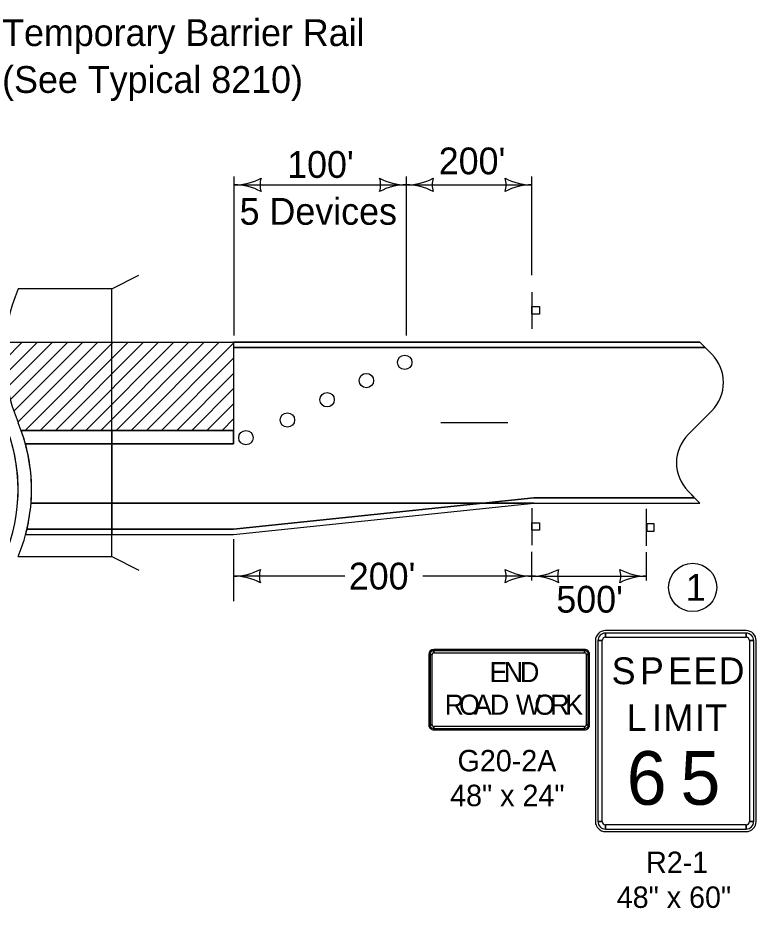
# Model space of a CAD drawing. Extents: x 10133 to 2270741, y 5363 to 1733450.
# Drawn here: x 27102 to 27653, y 11292 to 11957 of the extents above; entities that cross this region are included whole.
import ezdxf

# ---------------------------------------------------------------- set-up
doc = ezdxf.new("R2010")
doc.units = 0
for name, color, linetype in [('dsnNonPlotable', 7, 'Continuous'), ('dsnShtPlotShapeBatchPrint', 7, 'Continuous'), ('dsnStdBorder', 7, 'Continuous'), ('Level 12', 7, 'Continuous'), ('Level 2', 7, 'Continuous')]:
    doc.layers.add(name, color=color, linetype=linetype)

msp = doc.modelspace()

# ---------------------------------------------------------------- linework, layer by layer
at = {"layer": 'dsnNonPlotable'}
for p, q in [((27172.24, 11754.35), (27192.24, 11764.35)), ((27619.84, 11705.56), (27611.06, 11714.35)), ((27602.27, 11645.56), (27619.84, 11663.13)), ((27104.47, 11648.61), (27263, 11648.61)), ((27263, 11648.61), (27263, 11638.61)), ((27263, 11638.61), (27107.64, 11638.61)), ((27611.06, 11594.35), (27602.27, 11603.13)), ((27111.86, 11594.35), (27487.22, 11594.35)), ((27263, 11574.84), (27487.2, 11598.35)), ((27108.85, 11574.84), (27263, 11574.84)), ((27102.24, 11554.35), (27172.24, 11554.35)), ((27172.24, 11554.35), (27192.24, 11544.35))]:
    msp.add_line(p, q, dxfattribs=at)
for points in [[(27172.24, 11554.35), (27172.24, 11754.35), (27102.24, 11754.35)], [(27263, 11710.35), (27615.06, 11710.35)], [(27417.67, 11654.35), (27467.67, 11654.35)], [(27417.67, 11654.35), (27467.67, 11654.35)], [(27104.47, 11648.61), (27117.54, 11648.61)], [(27120.71, 11638.61), (27107.64, 11638.61)], [(27487.2, 11598.35), (27607.06, 11598.35)]]:
    msp.add_lwpolyline(points, dxfattribs=at)
for centre, radius, start, end in [((27222.24, 11704.35), 130, 157.38014, 202.61987), ((27598.63, 11684.35), 30, 315, 45), ((26972.24, 11604.35), 130, 337.38014, 22.61987), ((26982.24, 11604.34), 130, 337.38014, 22.61987), ((27623.48, 11624.35), 30, 135, 225)]:
    msp.add_arc(centre, radius, start, end, dxfattribs=at)
at = {"layer": 'dsnShtPlotShapeBatchPrint'}
msp.add_circle((27605.63, 11531.37), 18, dxfattribs=at)
at = {"layer": 'dsnStdBorder'}
for p, q in [((27485.62, 11751.88), (27485.62, 11724.38)), ((27092.28, 11701.37), (27105.26, 11714.35)), ((27092.96, 11690.73), (27116.57, 11714.35)), ((27094.38, 11680.85), (27127.88, 11714.35)), ((27096.44, 11671.59), (27139.2, 11714.35)), ((27099.04, 11662.87), (27150.51, 11714.35)), ((27102.12, 11654.64), (27161.82, 11714.35)), ((27107.4, 11648.61), (27173.14, 11714.35)), ((27118.72, 11648.61), (27184.45, 11714.35)), ((27130.03, 11648.61), (27195.77, 11714.35)), ((27141.35, 11648.61), (27207.08, 11714.35)), ((27152.66, 11648.61), (27218.39, 11714.35)), ((27163.97, 11648.61), (27229.71, 11714.35)), ((27175.29, 11648.61), (27241.02, 11714.35)), ((27186.6, 11648.61), (27252.33, 11714.35)), ((27197.91, 11648.61), (27263, 11713.7)), ((27263, 11714.35), (27263, 11648.61)), ((27209.23, 11648.61), (27263, 11702.39)), ((27220.54, 11648.61), (27263, 11691.07)), ((27231.86, 11648.61), (27263, 11679.76)), ((27243.17, 11648.61), (27263, 11668.45)), ((27254.48, 11648.61), (27263, 11657.13)), ((27172.24, 11648.61), (27172.24, 11638.61)), ((27263, 11638.61), (27263, 11648.61)), ((27172.24, 11638.61), (27263, 11638.61)), ((27263, 11574.84), (27487.2, 11598.35)), ((27487.2, 11598.35), (27607.06, 11598.35)), ((27485.62, 11590.44), (27485.62, 11562.94)), ((27571.27, 11562.46), (27571.27, 11589.96)), ((27645.52, 11499.13), (27540.52, 11499.13)), ((27540.52, 11494.13), (27540.52, 11497.26)), ((27645.52, 11497.26), (27645.52, 11494.13)), ((27533.02, 11491.63), (27533.02, 11356.63)), ((27534.89, 11491.63), (27538.02, 11491.63)), ((27648.02, 11491.63), (27651.14, 11491.63)), ((27653.02, 11356.63), (27653.02, 11491.63)), ((27408.68, 11481.31), (27408.68, 11428.81)), ((27409.62, 11481.31), (27411.18, 11481.31)), ((27524.93, 11485.06), (27412.43, 11485.06)), ((27412.43, 11482.56), (27412.43, 11484.12)), ((27524.93, 11484.12), (27524.93, 11482.56)), ((27526.18, 11481.31), (27527.75, 11481.31)), ((27528.68, 11428.81), (27528.68, 11481.31)), ((27411.18, 11428.81), (27409.62, 11428.81)), ((27412.43, 11426), (27412.43, 11427.56)), ((27524.93, 11427.56), (27524.93, 11426)), ((27527.75, 11428.81), (27526.18, 11428.81)), ((27412.43, 11425.06), (27524.93, 11425.06)), ((27538.02, 11356.63), (27534.89, 11356.63)), ((27540.52, 11351.01), (27540.52, 11354.13)), ((27645.52, 11354.13), (27645.52, 11351.01)), ((27651.14, 11356.63), (27648.02, 11356.63)), ((27540.52, 11349.13), (27645.52, 11349.13))]:
    msp.add_line(p, q, dxfattribs=at)
for points in [[(27485.71, 11735.43), (27485.71, 11741.06), (27491.34, 11741.06), (27491.34, 11735.43)], [(27485.71, 11573.99), (27485.71, 11579.61), (27491.34, 11579.61), (27491.34, 11573.99)], [(27571.36, 11578.91), (27571.36, 11573.29), (27576.99, 11573.29), (27576.99, 11578.91)], [(27645.52, 11497.26), (27540.52, 11497.26), (27540.52, 11494.13), (27645.52, 11494.13), (27645.52, 11497.26)], [(27534.89, 11491.63), (27534.89, 11356.63), (27538.02, 11356.63), (27538.02, 11491.63), (27534.89, 11491.63)], [(27651.14, 11356.63), (27651.14, 11491.63), (27648.02, 11491.63), (27648.02, 11356.63), (27651.14, 11356.63)], [(27409.62, 11481.31), (27409.62, 11428.81), (27411.18, 11428.81), (27411.18, 11481.31), (27409.62, 11481.31)], [(27524.93, 11484.12), (27412.43, 11484.12), (27412.43, 11482.56), (27524.93, 11482.56), (27524.93, 11484.12)], [(27527.75, 11428.81), (27527.75, 11481.31), (27526.18, 11481.31), (27526.18, 11428.81), (27527.75, 11428.81)], [(27412.43, 11426), (27524.93, 11426), (27524.93, 11427.56), (27412.43, 11427.56), (27412.43, 11426)], [(27540.52, 11351.01), (27645.52, 11351.01), (27645.52, 11354.13), (27540.52, 11354.13), (27540.52, 11351.01)]]:
    msp.add_lwpolyline(points, close=True, dxfattribs=at)
msp.add_lwpolyline([(27263, 11648.61), (27254.48, 11648.61), (27243.17, 11648.61), (27231.86, 11648.61), (27220.54, 11648.61), (27209.23, 11648.61), (27197.91, 11648.61), (27186.6, 11648.61), (27175.29, 11648.61), (27172.24, 11648.61)], dxfattribs=at)
for centre in [(27390.73, 11699.38), (27390.73, 11699.38), (27362.14, 11685.77), (27362.14, 11685.77), (27332.81, 11671.46), (27332.81, 11671.46), (27303.19, 11656.36), (27303.19, 11656.36), (27272.23, 11643.14), (27272.23, 11643.14)]:
    msp.add_circle(centre, 5.37, dxfattribs=at)
for centre, radius, start, end in [((27540.52, 11491.63), 7.5, 90.00021, 179.99985), ((27645.52, 11491.63), 7.5, 0, 90.00021), ((27540.52, 11491.63), 5.62, 90.00021, 179.99985), ((27540.52, 11491.63), 2.5, 90.00021, 179.99985), ((27645.52, 11491.63), 5.62, 0, 90.00021), ((27645.52, 11491.63), 2.5, 0, 90.00021), ((27412.43, 11481.31), 3.75, 90.00021, 179.99985), ((27412.43, 11481.31), 2.81, 90.00021, 179.99985), ((27412.43, 11481.31), 1.25, 90.00021, 179.99985), ((27524.93, 11481.31), 3.75, 0, 90.00021), ((27524.93, 11481.31), 2.81, 0, 90.00021), ((27524.93, 11481.31), 1.25, 0, 90.00021), ((27412.43, 11428.81), 3.75, 179.99985, 270.00006), ((27412.43, 11428.81), 2.81, 179.99985, 270.00006), ((27412.43, 11428.81), 1.25, 179.99985, 270.00006), ((27524.93, 11428.81), 3.75, 270.00006, 0.00027), ((27524.93, 11428.81), 2.81, 270.00006, 0.00027), ((27524.93, 11428.81), 1.25, 270.00006, 0.00027), ((27540.52, 11356.63), 7.5, 179.99985, 270.00006), ((27540.52, 11356.63), 5.62, 179.99985, 270.00006), ((27540.52, 11356.63), 2.5, 179.99985, 270.00006), ((27645.52, 11356.63), 7.5, 270.00006, 0.00027), ((27645.52, 11356.63), 5.62, 270.00006, 0.00027), ((27645.52, 11356.63), 2.5, 270.00006, 0.00027)]:
    msp.add_arc(centre, radius, start, end, dxfattribs=at)
at = {"layer": 'Level 12'}
for p, q in [((27263.54, 11719.39), (27263.54, 11838.1)), ((27392.03, 11719.39), (27392.03, 11838.1)), ((27485.62, 11764.38), (27485.62, 11838.1)), ((27263.54, 11831.87), (27485.62, 11831.87)), ((27263, 11567.42), (27263, 11521.18)), ((27485.62, 11536.6), (27485.62, 11557.84)), ((27571.27, 11536.6), (27571.27, 11557.57)), ((27345.96, 11539.8), (27263, 11539.8)), ((27485.62, 11539.8), (27404.29, 11539.8)), ((27485.62, 11539.8), (27571.27, 11539.8))]:
    msp.add_line(p, q, dxfattribs=at)
for centre, radius, start, end in [((27263.54, 11874.37), 42.5, 270, 298.07249), ((27263.54, 11789.37), 42.5, 61.92751, 90), ((27299.17, 11831.87), 16.42, 162.26665, 197.73335), ((27356.33, 11831.87), 16.42, 342.26665, 17.73335), ((27391.97, 11874.37), 42.5, 241.92751, 270), ((27391.97, 11789.37), 42.5, 90, 118.07249), ((27391.97, 11874.37), 42.5, 270, 298.07249), ((27391.97, 11789.37), 42.5, 61.92751, 90), ((27427.61, 11831.87), 16.42, 162.26665, 197.73335), ((27449.98, 11831.87), 16.42, 342.26665, 17.73335), ((27485.62, 11874.37), 42.5, 241.92751, 270), ((27485.62, 11789.37), 42.5, 90, 118.07249), ((27263, 11582.3), 42.5, 270, 298.07249), ((27263, 11497.3), 42.5, 61.92751, 90), ((27298.64, 11539.8), 16.42, 162.26665, 197.73335), ((27449.98, 11539.8), 16.42, 342.26665, 17.73335), ((27485.62, 11582.3), 42.5, 241.92751, 270), ((27485.62, 11497.3), 42.5, 90, 118.07249), ((27485.62, 11582.3), 42.5, 270, 298.07249), ((27485.62, 11497.3), 42.5, 61.92751, 90), ((27521.25, 11539.8), 16.42, 162.26665, 197.73335), ((27535.63, 11539.8), 16.42, 342.26665, 17.73335), ((27571.27, 11582.3), 42.5, 241.92751, 270), ((27571.27, 11497.3), 42.5, 90, 118.07249)]:
    msp.add_arc(centre, radius, start, end, dxfattribs=at)
at = {"layer": 'Level 2'}
for p, q in [((27092.63, 11714.35), (27611.06, 11714.35)), ((27611.06, 11714.35), (27263, 11714.35)), ((27263, 11714.35), (27263, 11710.35)), ((27615.06, 11710.35), (27611.06, 11714.35)), ((27263, 11710.35), (27615.06, 11710.35)), ((27615.06, 11710.35), (27263, 11710.35)), ((27263, 11710.35), (27263, 11702.39)), ((27619.84, 11705.56), (27615.06, 11710.35)), ((27263, 11702.39), (27263, 11691.07)), ((27263, 11691.07), (27263, 11679.76)), ((27602.27, 11645.56), (27619.84, 11663.13)), ((27172.24, 11638.61), (27172.24, 11648.61)), ((27263, 11648.61), (27263, 11638.61)), ((27107.64, 11638.61), (27120.71, 11638.61)), ((27120.71, 11638.61), (27172.24, 11638.61)), ((27172.24, 11594.35), (27172.24, 11638.61)), ((27263, 11638.61), (27172.24, 11638.61)), ((27172.24, 11638.61), (27172.24, 11594.35)), ((27607.06, 11598.35), (27602.27, 11603.13)), ((27172.24, 11594.35), (27111.86, 11594.35)), ((27111.86, 11594.35), (27172.24, 11594.35)), ((27405.4, 11594.35), (27172.24, 11594.35)), ((27172.24, 11594.35), (27172.24, 11574.84)), ((27172.24, 11574.84), (27172.24, 11594.35)), ((27172.24, 11594.35), (27449.06, 11594.35)), ((27263, 11570.84), (27487.2, 11594.35)), ((27263, 11574.84), (27449.05, 11594.35)), ((27263, 11570.84), (27487.2, 11594.35)), ((27449.05, 11594.35), (27263, 11574.84)), ((27405.4, 11594.35), (27611.06, 11594.35)), ((27449.05, 11594.35), (27405.4, 11594.35)), ((27487.2, 11598.35), (27449.05, 11594.35)), ((27487.2, 11594.35), (27449.05, 11594.35)), ((27449.05, 11594.35), (27611.06, 11594.35)), ((27449.06, 11594.35), (27487.2, 11598.35)), ((27607.06, 11598.35), (27487.2, 11598.35)), ((27487.2, 11598.35), (27607.06, 11598.35)), ((27611.06, 11594.35), (27607.06, 11598.35)), ((27108.85, 11574.84), (27121.91, 11574.84)), ((27121.91, 11574.84), (27108.85, 11574.84)), ((27121.91, 11574.84), (27172.24, 11574.84)), ((27172.24, 11574.84), (27121.91, 11574.84)), ((27172.24, 11574.84), (27263, 11574.84)), ((27263, 11574.84), (27172.24, 11574.84)), ((27172.24, 11574.84), (27172.24, 11570.84)), ((27172.24, 11570.84), (27172.24, 11574.84)), ((27107.85, 11570.84), (27172.24, 11570.84)), ((27107.85, 11570.84), (27263, 11570.84)), ((27107.85, 11570.84), (27120.91, 11570.84)), ((27172.24, 11570.84), (27263, 11570.84))]:
    msp.add_line(p, q, dxfattribs=at)
for points in [[(27615.06, 11710.35), (27615.06, 11710.35)], [(27615.06, 11710.35), (27615.06, 11710.35)], [(27263, 11679.76), (27263, 11668.45), (27263, 11657.13), (27263, 11648.61)], [(27172.24, 11648.61), (27163.97, 11648.61), (27152.66, 11648.61), (27141.35, 11648.61), (27130.03, 11648.61), (27118.72, 11648.61), (27117.54, 11648.61), (27107.4, 11648.61), (27104.47, 11648.61)], [(27172.24, 11638.61), (27120.71, 11638.61), (27107.64, 11638.61)], [(27405.4, 11594.35), (27405.4, 11594.35)], [(27607.06, 11598.35), (27607.06, 11598.35)], [(27607.06, 11598.35), (27607.06, 11598.35)]]:
    msp.add_lwpolyline(points, dxfattribs=at)
for centre, radius, start, end in [((27598.63, 11684.35), 30, 315, 45), ((26982.24, 11604.34), 130, 15.28322, 19.90817), ((27623.48, 11624.35), 30, 135, 225), ((26972.24, 11604.35), 130, 355.58827, 15.28231), ((26982.24, 11604.34), 130, 355.58916, 15.28322), ((26982.24, 11604.34), 130, 346.88255, 355.58916), ((26982.24, 11604.34), 130, 345.06535, 346.88255)]:
    msp.add_arc(centre, radius, start, end, dxfattribs=at)

# ---------------------------------------------------------------- texts
at = {"layer": 'dsnShtPlotShapeBatchPrint'}
msp.add_text('1', height=20, dxfattribs=at).set_placement((27600.43, 11521.37))
at = {"layer": 'dsnStdBorder'}
for s, height, p in [('S', 20, (27545.15, 11459.13)), ('P', 20, (27566.24, 11459.13)), ('E', 20, (27587.33, 11459.13)), ('E', 20, (27606.14, 11459.13)), ('D', 20, (27624.95, 11459.13)), ('E', 15, (27454.01, 11460.68)), ('N', 15, (27464.63, 11460.68)), ('D', 15, (27476.72, 11460.68)), ('R', 15, (27420.55, 11436.31)), ('O', 15, (27431.23, 11436.31)), ('A', 15, (27442.39, 11436.31)), ('D', 15, (27454.24, 11436.31)), ('W', 15, (27473.7, 11436.31)), ('O', 15, (27487.43, 11436.31)), ('R', 15, (27499.2, 11436.31)), ('K', 15, (27510.5, 11436.31)), ('L', 20, (27556.4, 11424.13)), ('I', 20, (27575.21, 11424.13)), ('M', 20, (27583.8, 11424.13)), ('I', 20, (27607.39, 11424.13)), ('T', 20, (27614.95, 11424.13)), ('G20-2A', 16, (27430.15, 11394.06)), ('6', 40, (27556.4, 11369.13)), ('5', 40, (27596.52, 11369.13)), ('48" x 24"', 16, (27424.62, 11368.06)), ('R2-1', 16, (27570.85, 11318.13)), ('48" x 60"', 16, (27548.95, 11292.13))]:
    msp.add_text(s, height=height, dxfattribs=at).set_placement(p)
at = {"layer": 'Level 12'}
for s, p in [('Temporary Barrier Rail', (27090.28, 11935.5)), ('(See Typical 8210)', (27090.28, 11900.5)), ("200'", (27416.12, 11839.74)), ("100'", (27302.99, 11837.09)), ('5 Devices', (27267.5, 11802.09)), ("200'", (27349, 11529.8)), ("500'", (27503.86, 11512.54))]:
    msp.add_text(s, height=20, dxfattribs=at).set_placement(p)

doc.saveas('drawing.dxf')
